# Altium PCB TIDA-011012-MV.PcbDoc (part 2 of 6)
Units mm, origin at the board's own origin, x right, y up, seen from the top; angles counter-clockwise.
Board outline 360 x 280 mm, 4 copper layers (Top Layer, Layer 1, Layer 2, Bottom Layer), stack 2.066 mm thick; 566 components, 345 nets, 1738 pads, 2486 vias.
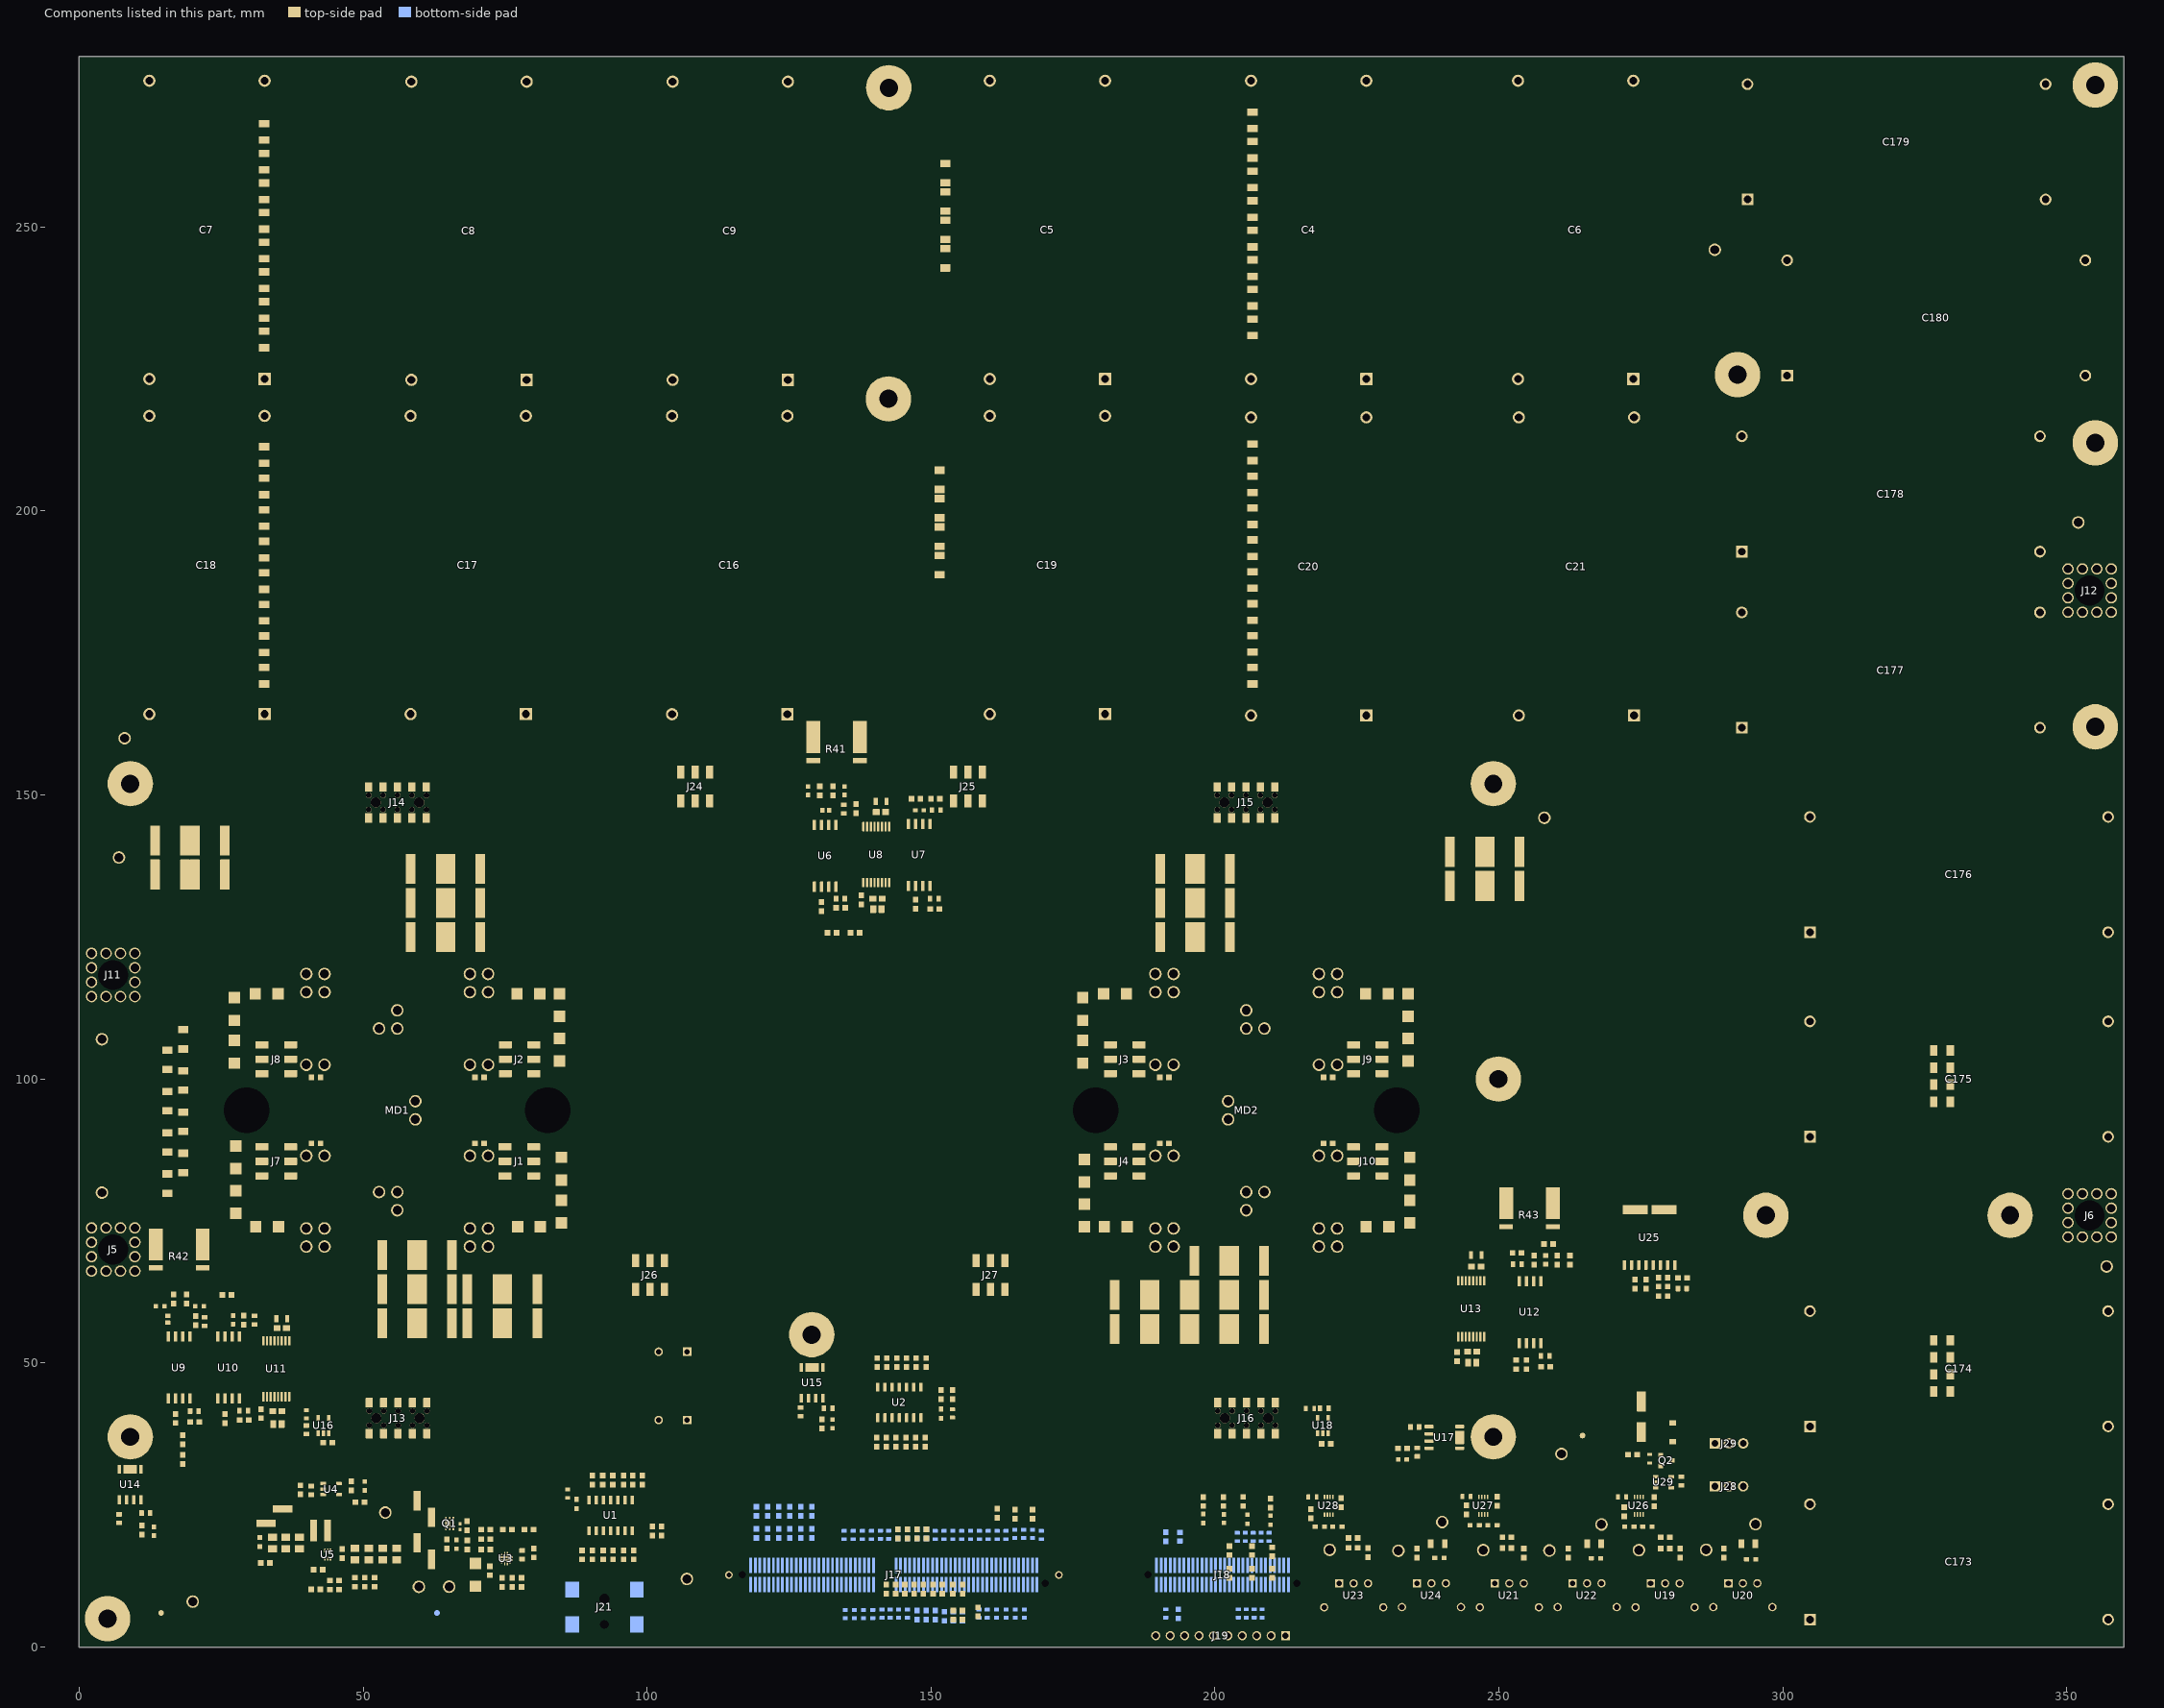
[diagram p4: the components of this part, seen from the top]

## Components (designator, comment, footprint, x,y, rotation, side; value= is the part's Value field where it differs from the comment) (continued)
R133 "ERJ-H3G0R00V" FP-ERJ-H3G0R00V_0603-MFG 209.522,19.382 r90 bottom value=0
R134 "RC0603FR-07470KL" 0603 79.214,20.703 r0 top value=470k
R135 "RC0603FR-0747KL" 0603 71.593,17.176 r180 top value=47.0k
R136 "RC0603FR-071K1L" 0603 76.246,11.376 r90 top value=1.10k
R137 "RC0603FR-075K6L" 0603 71.586,18.961 r0 top value=5.60k
R138 "RC0603FR-0711KL" 0603 75.385,20.693 r0 top value=11.0k
R139 "RC0603FR-0747KL" 0603 68.335,18.007 r270 top value=47.0k
R140 "RC0603FR-072KL" 0603 64.771,18.161 r270 top value=2.00k
R141 "RC0603FR-0747KL" 0603 71.588,20.693 r0 top value=47.0k
R142 "RC0603FR-0715KL" 0603 68.321,21.374 r270 top value=15.0k
R143 "RC0603FR-0747KL" 0603 52.016,11.423 r270 top value=47.0k
R144 "RC0603FR-07220KL" 0603 44.943,10.123 r0 top value=220k
R145 "RG1608P-103-B-T5" 0603 50.275,11.423 r270 top value=10.0k
R146 "RC0603FR-0730KL" 0603 41.644,10.148 r0 top value=30.0k
R147 "CRCW0603499RFKEAC" 0603 32.802,14.815 r180 top value=499
R148 "CRCW0603499RFKEAC" 0603 49.411,25.501 r0 top value=499
R149 "ERJ-3EKF1002V" 0603 153.922,5.621 r270 top value=10.0k
R150 "ERJ-3EKF1002V" 0603 155.522,5.621 r270 top value=10.0k
R151 "TNPW060310R0BEEA" 0603 132.731,150.763 r270 top value=10.0
R152 "TNPW060310R0BEEA" 0603 130.413,150.763 r270 top value=10.0
R153 "RC0603FR-0740R2L" 0603 130.731,130.391 r270 top value=40.2
R154 "RC0603FR-07100RL" 0603 132.566,125.743 r180 top value=100
R155 "CHV1206-FX-1504ELF" FP-CHV1206-FX-1504ELF_1206-MFG 152.5,259.5 r270 top value=1.5M
R156 "CHV1206-FX-1504ELF" FP-CHV1206-FX-1504ELF_1206-MFG 152.5,254.5 r270 top value=1.5M
R157 "CHV1206-FX-1504ELF" FP-CHV1206-FX-1504ELF_1206-MFG 152.5,249.5 r270 top value=1.5M
R158 "CHV1206-FX-1504ELF" FP-CHV1206-FX-1504ELF_1206-MFG 152.5,244.5 r270 top value=1.5M
R159 "CHV1206-FX-1504ELF" FP-CHV1206-FX-1504ELF_1206-MFG 151.5,205.5 r270 top value=1.5M
R160 "CHV1206-FX-1504ELF" FP-CHV1206-FX-1504ELF_1206-MFG 151.5,200.5 r270 top value=1.5M
R161 "CHV1206-FX-1504ELF" FP-CHV1206-FX-1504ELF_1206-MFG 151.5,195.5 r270 top value=1.5M
R162 "CHV1206-FX-1504ELF" FP-CHV1206-FX-1504ELF_1206-MFG 151.5,190.5 r270 top value=1.5M
R163 "RC0603FR-0740R2L" 0603 147.266,130.807 r270 top value=40.2
R164 "RC0603FR-074K7L" 0603 147.327,149.343 r0 top value=4.70k
R165 "RC0603JR-0718KL" 0603 137.728,131.528 r270 top value=18k
R166 "TNPW060310R0BEEA" 0603 16.6,61.3 r270 top value=10.0
R167 "TNPW060310R0BEEA" 0603 18.938,61.3 r270 top value=10.0
R168 "RC0603FR-0740R2L" 0603 16.965,40.25 r270 top value=40.2
R169 "RC0603FR-07100RL" 0603 18.235,36.521 r90 top value=100
R170 "CHV1206-FX-1504ELF" FP-CHV1206-FX-1504ELF_1206-MFG 18.319,107 r270 top locked value=1.5M
R171 "CHV1206-FX-1504ELF" FP-CHV1206-FX-1504ELF_1206-MFG 15.5,103.371 r270 top locked value=1.5M
R172 "CHV1206-FX-1504ELF" FP-CHV1206-FX-1504ELF_1206-MFG 18.319,99.743 r270 top locked value=1.5M
R173 "CHV1206-FX-1504ELF" FP-CHV1206-FX-1504ELF_1206-MFG 15.5,96.114 r270 top locked value=1.5M
R174 "CHV1206-FX-1504ELF" FP-CHV1206-FX-1504ELF_1206-MFG 18.319,92.486 r270 top locked value=1.5M
R175 "CHV1206-FX-1504ELF" FP-CHV1206-FX-1504ELF_1206-MFG 15.5,88.857 r270 top locked value=1.5M
R176 "CHV1206-FX-1504ELF" FP-CHV1206-FX-1504ELF_1206-MFG 18.319,85.229 r270 top locked value=1.5M
R177 "CHV1206-FX-1504ELF" FP-CHV1206-FX-1504ELF_1206-MFG 15.5,81.6 r270 top locked value=1.5M
R178 "RC0603FR-0740R2L" 0603 25.665,40.221 r270 top value=40.2
R179 "RC0603FR-074K7L" 0603 26,62 r180 top value=4.70k
R180 "RC0603JR-0718KL" 0603 32,41.096 r270 top value=18k
R181 "TNPW060310R0BEEA" 0603 262.5,68.122 r270 top value=10.0
R182 "TNPW060310R0BEEA" 0603 258.699,70.95 r180 top value=10.0
R183 "RC0603FR-0740R2L" 0603 254.83,49.728 r270 top value=40.2
R184 "ERJ-3EKF1001V" 0603 253.182,69.397 r0 top value=1.00k
R185 "RC0603JR-0718KL" 0603 242.615,51.153 r270 top value=18k
R186 "ERJ-3GEYJ470V" 0603 11.016,20.59 r90 top value=47
R187 "RT0603BRD07200RL" 0603 273.525,33.855 r0 top value=200
R188 "CRCW060310K0JNEBC" FP-CRCW060310K0JNEBC_0603-MFG 276.53,33.13 r90 top value=10k
R189 "ERJ-3GEYJ470V" 0603 130.81,39.31 r90 top value=47
R190 "RC0603FR-07680RL" 0603 43.754,36 r0 top value=680
R191 "ERJ-3GEYJ470V" 0603 233,35 r0 top value=47
R192 "RC0603FR-07680RL" 0603 219.559,35.777 r0 top value=680
R193 "RC0603FR-07390RL" 0603 279.3,19.35 r0 top value=390
R194 "RC0603FR-07120RL" 0603 281.917,16.525 r270 top value=120
R195 "CRCW060347R0JNEA" 0603 289.606,16.525 r90 top value=47
R196 "RC0603FR-07390RL" 0603 251.404,19.325 r0 top value=390
R197 "RC0603FR-07120RL" 0603 254.369,16.55 r270 top value=120
R198 "CRCW060347R0JNEA" 0603 262.187,16.55 r90 top value=47
R199 "CRCW060368R1FKEA" 0603 275.865,63.925 r270 top value=68.1
R200 "CRCW12064R70JNEA" 1206 328,54 r0 top value=4.7
R201 "CRCW12064R70JNEA" 1206 328,51 r0 top value=4.7
R202 "RC0603JR-078K2L" 0603 278.895,61.775 r180 top value=8.2k
R203 "RC0603JR-071K2L" 0603 278.895,63.45 r0 top value=1.2k
R204 "ERJ-3EKF1002V" 0603 102.546,20.432 r90 top value=10.0k
R205 "ERJ-3EKF1002V" 0603 153.763,44.458 r90 top value=10.0k
R206 "CRCW12064R70JNEA" 1206 328,48 r0 top value=4.7
R207 "CRCW12064R70JNEA" 1206 328,45 r0 top value=4.7
R208 "RC0603FR-07390RL" 0603 224.328,17.463 r0 top value=390
R209 "RC0603FR-07120RL" 0603 226.951,16.609 r270 top value=120
R210 "CRCW060347R0JNEA" 0603 235.561,16.553 r90 top value=47
R211 "CRCW12064R70JNEA" 1206 328,105 r0 top value=4.7
R212 "CRCW12064R70JNEA" 1206 328,102 r0 top value=4.7
R213 "CRCW12064R70JNEA" 1206 328,99 r0 top value=4.7
R214 "CRCW12064R70JNEA" 1206 328,96 r0 top value=4.7
R215 "ERJ-H3G0R00V" FP-ERJ-H3G0R00V_0603-MFG 271.681,26.445 r0 top value=0
R216 "ERJ-H3G0R00V" FP-ERJ-H3G0R00V_0603-MFG 244.28,26.495 r0 top value=0
R217 "ERJ-H3G0R00V" FP-ERJ-H3G0R00V_0603-MFG 217.152,26.419 r0 top value=0
R218 "ERJ-H3G0R00V" FP-ERJ-H3G0R00V_0603-MFG 40,41 r270 top value=0
R219 "ERJ-H3G0R00V" FP-ERJ-H3G0R00V_0603-MFG 216.725,42 r0 top value=0
TP1 "5010" Keystone5010 65.146,10.623 r0 top
TP2 "5011" Keystone5011 59.808,10.596 r0 top
TP3 "5010" Keystone5010 53.895,23.678 r0 top
TP4 "5122" Keystone5122 274.649,17.075 r0 top
TP5 "5122" Keystone5122 295.158,21.641 r0 top
TP6 "5122" Keystone5122 286.492,17.112 r0 top
TP7 "5122" Keystone5122 247.231,17.075 r0 top
TP8 "5122" Keystone5122 268.06,21.578 r0 top
TP9 "5122" Keystone5122 258.87,17 r0 top
TP10 "5122" Keystone5122 220.19,17.112 r0 top
TP11 "5122" Keystone5122 240,22 r0 top
TP12 "5122" Keystone5122 232.3,16.95 r0 top
TP13 "5010" Keystone5010 7,139 r0 top
TP14 "5010" Keystone5010 258,146 r0 top
TP15 "5122" Keystone5122 4,80 r0 top
TP16 "5122" Keystone5122 357,67 r0 top
TP17 "5011" Keystone5011 8,160 r0 top
TP18 "5011" Keystone5011 288,246 r0 top
TP19 "5122" Keystone5122 4,107 r0 top
TP20 "5122" Keystone5122 352,198 r0 top
TP21 "5011" Keystone5011 107,12 r0 top
TP22 "5011" Keystone5011 20,8 r0 top
TP23 "5011" Keystone5011 261,34 r0 top
U1 "SN74HCS126DR" D0014A-MFG 93.546,23.184 r90 top
U2 "SN74HCS126DR" D0014A-MFG 144.432,43.075 r270 top
U3 "TPS259474LRPWT" RPW0010A-MFG 75.16,15.574 r270 top
U4 "TLV75533PDBVR" DBV0005A_N 44.357,27.815 r0 top
U5 "TPS563203DRLR" DRL0006A-MFG 43.759,16.301 r270 top
U6 "AMC0306M05-Q1" DWV0008A-MFG 131.366,139.313 r270 top locked
U7 "AMC1336DWVR" DWV0008A 147.901,139.463 r270 top locked
U8 "UCC33421DHAR" DHA0016A-MFG 140.366,139.513 r90 top locked
U9 "AMC0306M05-Q1" DWV0008A-MFG 17.6,49.2 r270 top locked
U10 "AMC1336DWVR" DWV0008A 26.3,49.2 r270 top
U11 "UCC33421DHAR" DHA0016A-MFG 34.7,49 r90 top locked
U12 "AMC23C12DWVR" DWV0008A-MFG 255.465,58.95 r270 top locked
U13 "UCC33421DHAR" DHA0016A-MFG 245.115,59.557 r90 top locked
U14 "ISOTMP35BEDFQRQ1" DFQ0007A-MFG 8.985,28.616 r90 top locked
U15 "ISOTMP35BEDFQRQ1" DFQ0007A-MFG 129.056,46.531 r90 top
U16 "TLV9001IDBVR" DBV0005A_N 43,39 r90 top
U17 "ISOTMP35BEDFQRQ1" DFQ0007A-MFG 240.383,36.913 r0 top
U18 "TLV9001IDBVR" DBV0005A_N 219,39 r90 top
U19 "TOTX1350(F)" FP-TOTX1350(F)_REC_OPT_PTH-MFG 279.248,7.151 r0 bottom
U20 "TORX1350A(F)" FP-TORX1350A(F)_OPTIC_RECIEVER_13MM0_13MM5-MFG 292.939,7.176 r0 bottom
U21 "TOTX1350(F)" FP-TOTX1350(F)_REC_OPT_PTH-MFG 251.829,7.151 r0 bottom
U22 "TORX1350A(F)" FP-TORX1350A(F)_OPTIC_RECIEVER_13MM0_13MM5-MFG 265.52,7.176 r0 bottom
U23 "TOTX1350(F)" FP-TOTX1350(F)_REC_OPT_PTH-MFG 224.411,7.151 r0 bottom
U24 "TORX1350A(F)" FP-TORX1350A(F)_OPTIC_RECIEVER_13MM0_13MM5-MFG 238.101,7.176 r0 bottom
U25 "TMCS1133B1QDVGR" DVG0010A-MFG 276.5,72.122 r270 top
U26 "TXU0202DCU" DCU0008A-MFG 274.631,24.895 r270 top
U27 "TXU0202DCU" DCU0008A-MFG 247.231,24.895 r270 top
U28 "TXU0202DCU" DCU0008A-MFG 220.019,24.869 r270 top
U29 "SN74LV1T34DBVR" DBV0005A_N 278.967,29.019 r0 top
ZZ1 "This Assembly Note is for PCB labels only" AssemblyNoteLabel 326.87,114.396 r90 top
ZZ2 "These assemblies are ESD sensitive, ESD precautions shall be observed." AssemblyNote 323.07,177.096 r90 top
ZZ3 "These assemblies must be clean and free from flux and all contaminants. Use of no clean flux is not acceptable." AssemblyNote 319.27,137.696 r90 top
ZZ4 "These assemblies must comply with workmanship standards IPC-A-610 Class 2, unless otherwise specified." AssemblyNote 315.47,145.996 r90 top

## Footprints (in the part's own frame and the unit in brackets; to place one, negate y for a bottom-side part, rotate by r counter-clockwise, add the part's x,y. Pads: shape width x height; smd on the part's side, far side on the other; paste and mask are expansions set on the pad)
0402L [mm] "0402 from SM-752 data"
  rect 0.6x0.5 smd: 1(-0.5,0) 2(0.5,0)
  body extent -0.55,-0.3 0.55,0.3, height 0.6
0603 [mm] "0603 from SM-752 data"
  rect 1x0.95 smd: 1(-0.8,0) 2(0.8,0)
  silkscreen extent -1.52,-0.69 1.52,0.69, body extent -0.87,-0.47 0.87,0.47, height 1
0805_HV [mil] "0805 with 30mil clearance between pads"
  rect 50x63 smd: 1(-40,0) 2(40,0)
  silkscreen extent -74,-40 74,40, body extent -43,-29 43,29, height 57
1206 [mm] "1206 from SM-752 data"
  rect 1.3x1.85 smd: 1(-1.45,0) 2(1.45,0)
  silkscreen extent -2.4,-1.21 2.4,1.21, body extent -1.7,-0.9 1.7,0.9, height 1.35
AssemblyNote [mm] "Assembly Note"
AssemblyNoteLabel [mm] "Assembly Note for PCB Labels"
CAPPR5-10x16 [mm] "Capacitor, Electrolytic, Radial; Body 10 x 16 mm (Dia.xH typ); Pin Spacing 5 mm (typ)"
  rect 1.5x1.5 hole 0.9: 1(-2.5,0)
  round 1.5 hole 0.9: 2(2.5,0)
  silkscreen extent -5,-5 5,5, body extent -5.02,-5.03 5.03,5.02, height 16.29
CE_Mark_5mm [mm] "Minimum text height for CE Mark"
  silkscreen extent -3.5,-2.5 3.5,2.5
controlCARD-120HSEC [mm] "Pads are not numbered according to Samtec datasheet."
  rect 0.5x2.724 smd: 1(-23.357,-1.678) 2(-23.357,1.722) 3(-22.557,-1.678) 4(-22.557,1.722) 5(-21.757,-1.678) 6(-21.757,1.722) 7(-20.957,-1.678) 8(-20.957,1.722) 9(-20.157,-1.678) 10(-20.157,1.722) 11(-19.357,-1.678) 12(-19.357,1.722) 13(-18.557,-1.678) 14(-18.557,1.722) 15(-17.757,-1.678) 16(-17.757,1.722) 17(-16.957,-1.678) 18(-16.957,1.722) 19(-16.157,-1.678) 20(-16.157,1.722) 21(-15.357,-1.678) 22(-15.357,1.722) 23(-14.557,-1.678) 24(-14.557,1.722) 25(-13.757,-1.678) 26(-13.757,1.722) 27(-12.957,-1.678) 28(-12.957,1.722) 29(-12.157,-1.678) 30(-12.157,1.722) 31(-11.357,-1.678) 32(-11.357,1.722) 33(-10.557,-1.678) 34(-10.557,1.722) 35(-9.757,-1.678) 36(-9.757,1.722) 37(-8.957,-1.678) 38(-8.957,1.722) 39(-8.157,-1.678) 40(-8.157,1.722) 41(-7.357,-1.678) 42(-7.357,1.722) 43(-6.557,-1.678) 44(-6.557,1.722) 45(-5.757,-1.678) 46(-5.757,1.722) 47(-4.957,-1.678) 48(-4.957,1.722) 49(-4.157,-1.678) 50(-4.157,1.722) 51(-3.357,-1.678) 52(-3.357,1.722) 53(-2.557,-1.678) 54(-2.557,1.722) 55(-1.757,-1.678) 56(-1.757,1.722) 57(2.243,-1.678) 58(2.243,1.722) 59(3.043,-1.678) 60(3.043,1.722) 61(3.843,-1.678) 62(3.843,1.722) 63(4.643,-1.678) 64(4.643,1.722) 65(5.443,-1.678) 66(5.443,1.722) 67(6.243,-1.678) 68(6.243,1.722) 69(7.043,-1.678) 70(7.043,1.722) 71(7.843,-1.678) 72(7.843,1.722) 73(8.643,-1.678) 74(8.643,1.722) 75(9.443,-1.678) 76(9.443,1.722) 77(10.243,-1.678) 78(10.243,1.722) 79(11.043,-1.678) 80(11.043,1.722) 81(11.843,-1.678) 82(11.843,1.722) 83(12.643,-1.678) 84(12.643,1.722) 85(13.443,-1.678) 86(13.443,1.722) 87(14.243,-1.678) 88(14.243,1.722) 89(15.043,-1.678) 90(15.043,1.722) 91(15.843,-1.678) 92(15.843,1.722) 93(16.643,-1.678) 94(16.643,1.722) 95(17.443,-1.678) 96(17.443,1.722) 97(18.243,-1.678) 98(18.243,1.722) 99(19.043,-1.678) 100(19.043,1.722) 101(19.843,-1.678) 102(19.843,1.722) 103(20.643,-1.678) 104(20.643,1.722) 105(21.443,-1.678) 106(21.443,1.722) 107(22.243,-1.678) 108(22.243,1.722) 109(23.043,-1.678) 110(23.043,1.722) 111(23.843,-1.678) 112(23.843,1.722) 113(24.643,-1.678) 114(24.643,1.722) 115(25.443,-1.678) 116(25.443,1.722) 117(26.243,-1.678) 118(26.243,1.722) 119(27.043,-1.678) 120(27.043,1.722)
  round 0.025 hole 1.27 unplated mask+0.876: 181(-24.857,0.022) 182(28.543,1.522)
  round 1.348 hole 0.84: 185(-27.207,0.022) 186(30.893,0.022)
  silkscreen extent -32.11,-3.86 35.8,3.9, body extent -31.75,-3.47 35.3,3.53, height 12.35
controlCARD-180HSEC-60pinAddon [mm] "Pads are not numbered according to datasheet."
  round 0.025 hole 1.27 unplated mask+0.876: 61(-13.1,0) 62(13.1,1.5)
  rect 0.5x2.724 smd: 121(-11.6,-1.7) 122(-11.6,1.7) 123(-10.8,-1.7) 124(-10.8,1.7) 125(-10,-1.7) 126(-10,1.7) 127(-9.2,-1.7) 128(-9.2,1.7) 129(-8.4,-1.7) 130(-8.4,1.7) 131(-7.6,-1.7) 132(-7.6,1.7) 133(-6.8,-1.7) 134(-6.8,1.7) 135(-6,-1.7) 136(-6,1.7) 137(-5.2,-1.7) 138(-5.2,1.7) 139(-4.4,-1.7) 140(-4.4,1.7) 141(-3.6,-1.7) 142(-3.6,1.7) 143(-2.8,-1.7) 144(-2.8,1.7) 145(-2,-1.7) 146(-2,1.7) 147(-1.2,-1.7) 148(-1.2,1.7) 149(-0.4,-1.7) 150(-0.4,1.7) 151(0.4,-1.7) 152(0.4,1.7) 153(1.2,-1.7) 154(1.2,1.7) 155(2,-1.7) 156(2,1.7) 157(2.8,-1.7) 158(2.8,1.7) 159(3.6,-1.7) 160(3.6,1.7) 161(4.4,-1.7) 162(4.4,1.7) 163(5.2,-1.7) 164(5.2,1.7) 165(6,-1.7) 166(6,1.7) 167(6.8,-1.7) 168(6.8,1.7) 169(7.6,-1.7) 170(7.6,1.7) 171(8.4,-1.7) 172(8.4,1.7) 173(9.2,-1.7) 174(9.2,1.7) 175(10,-1.7) 176(10,1.7) 177(10.8,-1.7) 178(10.8,1.7) 179(11.6,-1.7) 180(11.6,1.7)
  silkscreen extent -14.68,-3.88 14.68,3.88, body extent -14.3,-3.5 14.3,3.5, height 7.95
CUI_PJ-002AH-SMT [mm] "CUI"
  rect 2.8x2.4 smd: 1(-3.05,5.7) 1A(3.05,5.7) 2(-3.05,-5.7) 3(3.05,-5.7)
  round 1 hole 1.6 unplated: MH1(-3.05,0)
  round 1.524 hole 1.8 unplated: MH2(1.45,0)
  silkscreen extent -8.05,-4.5 6.75,5.45, body extent -8.05,-6.3 6.75,6.3, height 11.2
D0014A-MFG [mm]
  rrect17% 1.55x0.6 smd paste-1000 mask+0: 1(-2.7,3.81) 2(-2.7,2.54) 3(-2.7,1.27) 4(-2.7,0) 5(-2.7,-1.27) 6(-2.7,-2.54) 7(-2.7,-3.81) 8(2.7,-3.81) 9(2.7,-2.54) 10(2.7,-1.27) 11(2.7,0) 12(2.7,1.27) 13(2.7,2.54) 14(2.7,3.81)
  silkscreen extent -4.15,-4.38 1.55,4.38, body extent -3.57,-4.62 3.57,4.62, height 0.25
DBV0005A_N [mm] "SOT23, 5-Leads, Body 2.9x1.6mm, Pitch 0.95mm, Lead Span 2.8mm, IPC Medium Density"
  rrect17% 1x0.6 smd: 1(-1.375,0.95) 2(-1.375,0) 3(-1.375,-0.95) 4(1.375,-0.95) 5(1.375,0.95)
  silkscreen extent -0.25,-1.55 0.25,1.55, body extent -1.42,-1.46 1.42,1.46, height 1.09
DCU0008A-MFG [mm]
  rrect33% 0.8x0.3 smd paste-1000 mask+0: 1(-1.55,0.75) 2(-1.55,0.25) 3(-1.55,-0.25) 4(-1.55,-0.75) 5(1.55,-0.75) 6(1.55,-0.25) 7(1.55,0.25) 8(1.55,0.75)
  silkscreen extent -2.62,-1.05 0.78,1.05, body extent -2.05,-1.3 2.05,1.3, height 0.25
DFQ0007A-MFG [mm]
  rrect17% 1.55x0.6 smd paste+0 mask+0: 1(-2.7,1.905) 2(-2.7,0.635) 3(-2.7,-0.635) 4(-2.7,-1.905) 5(2.7,-1.905) 7(2.7,1.905)
  rrect6% 1.55x2.36 smd paste+0 mask+0: 6(2.7,0)
  silkscreen extent -4.14,-2.5 1.55,2.5, body extent -3.57,-2.75 3.57,2.75, height 0.25
DHA0016A-MFG [mm]
  rrect24% 1.65x0.41 smd paste+0 mask+0: 1(-4.925,2.275) 2(-4.925,1.625) 3(-4.925,0.975) 4(-4.925,0.325) 5(-4.925,-0.325) 6(-4.925,-0.975) 7(-4.925,-1.625) 8(-4.925,-2.275) 9(4.925,-2.275) 10(4.925,-1.625) 11(4.925,-0.975) 12(4.925,-0.325) 13(4.925,0.325) 14(4.925,0.975) 15(4.925,1.625) 16(4.925,2.275)
  silkscreen extent -6.42,-2.98 3.5,2.98, body extent -5.85,-3.22 5.85,3.22, height 0.25
DQK0006C [mm] "WSON"
  rrect12% 0.9x0.86 on Top Paste: 0(0,0.325)
  rrect34% 0.7x0.29 on Top Paste: 0(0.095,-0.65)
  rrect33% 0.45x0.3 smd: 1(-0.975,0.65) 2(-0.975,0) 3(-0.975,-0.65) 4(0.975,-0.65) 5(0.975,0) 6(0.975,0.65)
  rrect33% 0.75x0.3 smd paste-0.15: 7(0.095,-0.65)
  rrect11% 1x0.95 smd paste-0.5: 8(0,0.325)
  silkscreen extent -1.15,-1.15 1.15,1.15, body extent -1,-1 1,1, height 0.82
DRL0006A-MFG [mm]
  rrect33% 0.67x0.3 smd paste+0 mask+0: 1(-0.74,0.5) 2(-0.74,0) 3(-0.74,-0.5) 4(0.74,-0.5) 5(0.74,0) 6(0.74,0.5)
  silkscreen extent -1.75,-1.05 0.65,1.05, body extent -1.17,-1.1 1.17,1.1, height 0.25
DVG0010A-MFG [mm]
  rrect6% 1.65x4.41 smd paste+0 mask+0: 1(-4.875,2.54) 2(-4.875,-2.54)
  rrect17% 1.65x0.6 smd paste+0 mask+0: 3(4.875,-4.445) 4(4.875,-3.175) 5(4.875,-1.905) 6(4.875,-0.635) 7(4.875,0.635) 8(4.875,1.905) 9(4.875,3.175) 10(4.875,4.445)
  silkscreen extent -6.37,-5.25 3.67,5.25, body extent -5.8,-5.5 5.8,5.5, height 0.25
DWV0008A [mm] "SOIC, 8-Leads, Body 5.95x7.6mm (max), Pitch 1.27mm"
  rrect17% 1.8x0.6 smd: 1(-5.45,1.905) 2(-5.45,0.635) 3(-5.45,-0.635) 4(-5.45,-1.905) 5(5.45,-1.905) 6(5.45,-0.635) 7(5.45,0.635) 8(5.45,1.905)
  silkscreen extent -6.25,-2.95 2.98,2.95, body extent -5.77,-2.92 5.77,2.93, height 2.67
DWV0008A-MFG [mm] "Recommended Land Pattern"
  rrect17% 1.8x0.6 smd paste+0 mask+0: 1(-5.45,1.905) 2(-5.45,0.635) 3(-5.45,-0.635) 4(-5.45,-1.905) 5(5.45,-1.905) 6(5.45,-0.635) 7(5.45,0.635) 8(5.45,1.905)
  silkscreen extent -7.1,-2.98 3.8,2.98, body extent -5.75,-2.93 5.75,2.93, height 2.8
FCC_disclaimer [mm]
Fiducial10-20 [mm]
  round 1 smd mask+0.5: 1(0,0)
  Top Layer keep-out circle w1.178: c0,0 r0.5
FP-0603ZC102KAT2A_0603-MFG [mm]
  rrect13% 0.8x0.75 smd paste+0 mask+0: 1(-0.75,0) 2(0.75,0)
  silkscreen extent -0.87,-0.77 0.87,0.77, body extent -1.25,-0.58 1.25,0.58, height 0.25
FP-06031C101JAT2A_0603-MFG [mm]
  rrect13% 0.8x0.75 smd paste+0 mask+0: 1(-0.75,0) 2(0.75,0)
  silkscreen extent -0.87,-0.77 0.87,0.77, body extent -1.25,-0.58 1.25,0.58, height 0.25
FP-0022111031_HDR3-MFG [mm]
  rrect5% 1.85x1.85 hole 1.2 paste-2539.97 mask+0: 1(2.5,0.3)
  round 1.85 hole 1.2 paste-2539.97 mask+0: 2(0,0.3) 3(-2.5,0.3)
  silkscreen extent -4.1,-3.1 4.7,3.1, body extent -3.5,-2.9 3.5,2.9, height 12.1
FP-74439324047_SMD2-MFG [mm] "Recommended Land Pattern"
  rrect8% 1.2x3.8 smd paste+0 mask+0: 1(-1.225,0) 2(1.225,0)
  silkscreen extent -2.88,-2.25 0.25,2.25, body extent -2.15,-2.15 2.15,2.15, height 3.2
FP-C4AQPEW5450M3BJ_RADIAL-MFG [mm] "Recommended Land Pattern"
  round 2.15 hole 1.4 paste-2539.97 mask+0: 1(-26.25,-10.15) 2(26.25,-10.15) 2(26.25,10.15)
  rrect5% 2.15x2.15 hole 1.4 paste-2539.97 mask+0: 1(-26.25,10.15)
  silkscreen extent -29.15,-22.75 29.15,22.75, body extent -28.75,-22.5 28.75,22.5, height 65.3
FP-C4ASPBW4250A3MJ_RADIAL-MFG [mm] "Recommended Land Pattern"
  round 2.05 hole 1.35 paste-2539.97 mask+0: 1(-26.25,-10.15) 2(26.25,-10.15) 2(26.25,10.15)
  rrect5% 2.05x2.05 hole 1.35 paste-2539.97 mask+0: 1(-26.25,10.15)
  silkscreen extent -28.75,-15 28.75,15, body extent -28.75,-15 28.75,15, height 45
FP-C0603C103J3GAC7867_0603-MFG [mm]
  rrect13% 0.75x0.9 smd paste+0 mask+0: 1(-0.6,0) 2(0.6,0)
  silkscreen extent -0.87,-0.82 0.87,0.82, body extent -1.2,-0.6 1.2,0.6, height 0.25
FP-C0603C153K5RACTU_0603-IPC_A [mil]
  rrect9% 47.5x41.66 smd paste+0 mask+0: 1(-32.51,0) 2(32.51,0)
  body extent -76,-41 76,41, height 10
FP-C2220X103KHRAC7800_2220-MFG [mm] "Recommended Land Pattern"
  rrect6% 1.7x5.3 smd paste+0 mask+0: 1(-2.65,0) 2(2.65,0)
  silkscreen extent -1.43,-2.7 1.43,2.7, body extent -2.95,-2.5 2.95,2.5, height 2.2
FP-CHV1206-FX-1504ELF_1206-MFG [mm]
  rrect8% 1.3x1.8 smd paste+0 mask+0: 1(-1.7,0) 2(1.7,0)
  silkscreen extent -0.67,-0.85 0.67,0.85, body extent -2.45,-1 2.45,1, height 0.25
FP-CL10B104KA8VPJC_0603-MFG [mm]
  rrect13% 0.79x1 smd paste+0 mask+0: 1(-0.755,0) 2(0.755,0)
  silkscreen extent -0.9,-0.87 0.9,0.87, body extent -1.25,-0.6 1.25,0.6, height 0.25
FP-CL10B105KA8VPJC_0603-MFG [mm]
  rrect13% 0.79x1 smd paste+0 mask+0: 1(-0.755,0) 2(0.755,0)
  silkscreen extent -0.9,-0.87 0.9,0.87, body extent -1.25,-0.6 1.25,0.6, height 0.25
FP-CRCW060310K0JNEBC_0603-MFG [mm]
  rrect20% 0.5x0.9 smd paste+0 mask+0: 1(-0.75,0) 2(0.75,0)
  silkscreen extent -0.13,-0.45 0.13,0.45, body extent -1.1,-0.55 1.1,0.55, height 0.25
FP-DMN3042L-13_SOT23-MFG [mm]
  rrect13% 0.9x0.8 smd paste+0 mask+0: 1(-1,0.95) 2(-1,-0.95) 3(1,0)
  silkscreen extent -0.7,-1.5 0.7,1.5, body extent -1.55,-1.6 1.55,1.6, height 0.25
FP-ERJ-H3G0R00V_0603-IPC_B [mm]
  rrect10% 0.957x0.962 smd paste+0 mask+0: 1(-0.751,0) 2(0.751,0)
  silkscreen extent -1.23,-0.88 1.23,0.88, body extent -0.8,-0.4 0.8,0.4, height 0.55
FP-ERJ-H3G0R00V_0603-MFG [mm]
  rrect15% 0.65x0.9 smd paste+0 mask+0: 1(-0.725,0) 2(0.725,0)
  silkscreen extent 0,-0.48 0,0.48, body extent -0.8,-0.4 0.8,0.4, height 0.55
FP-G4H22MT33GB4_SiCPAK-G+_MODIFIED-MFG [mm] "Recommended Land Pattern Modified"
  round 2.2 hole 1.6 paste-2539.97 mask+0: AC1(20.8,12.8) AC1(20.8,16) AC1(24,12.8) AC1(24,16) AC2(-24,12.8) AC2(-24,16) AC2(-20.8,12.8) AC2(-20.8,16) DC1+(20.8,-16) DC1+(20.8,-12.8) DC1+(24,-16) DC1+(24,-12.8) DC1-(14.4,0) DC1-(14.4,3.2) DC1-(17.6,0) DC2+(-24,-16) DC2+(-24,-12.8) DC2+(-20.8,-16) DC2+(-20.8,-12.8) DC2-(-17.6,0) DC2-(-14.4,0) DC2-(-14.4,3.2) G1(8,-12.8) G2(8,12.8) G3(-8,-12.8) G4(-8,12.8) KS1(8,-16) KS2(8,16) KS3(-8,-16) KS4(-8,16) T1(-1.6,-3.2) T2(1.6,-3.2)
  round 4.6 hole 8 unplated paste-2539.97 mask+0: ""(0,-26.5) ""(0,26.5)
  silkscreen extent -28.45,-24.1 29.12,24.1, body extent -28.35,-32.49 28.35,32.51, height 12.9
FP-GMC10X7R104K25NT_0603-MFG [mil]
  rrect13% 35x30 smd paste+0 mask+0: 1(-32.5,0) 2(32.5,0)
  silkscreen extent -35,-31 35,31, body extent -54,-24 54,24, height 10
FP-GRT21BD71A226ME13L_0805-MFG [mm]
  rrect14% 0.7x1.3 smd paste+0 mask+0: 1(-0.95,0) 2(0.95,0)
  silkscreen extent -0.23,-0.72 0.23,0.72, body extent -1.4,-0.82 1.4,0.82, height 0.25
FP-HLE-105-02-G-DV-BE-A_CONN_RCPT_10-MFG [mm] "Recommended Land Pattern"
  rrect8% 1.27x1.68 smd paste+0 mask+0: 1(5.08,-2.72) 2(5.08,2.72) 3(2.54,-2.72) 4(2.54,2.72) 5(0,-2.72) 6(0,2.72) 7(-2.54,-2.72) 8(-2.54,2.72) 9(-5.08,-2.72) 10(-5.08,2.72)
  round 0.97 hole 0.97 unplated paste-2539.97 mask+0: ""(-5.08,-1.27) ""(-5.08,1.27) ""(-2.54,-1.27) ""(-2.54,1.27) ""(0,1.27) ""(0,-1.27) ""(2.54,-1.27) ""(2.54,1.27) ""(5.08,-1.27) ""(5.08,1.27)
  round 1.78 hole 1.78 unplated paste-2539.97 mask+0: ""(-3.81,0) ""(3.81,0)
  silkscreen extent -6.45,-3.43 6.45,2.61, body extent -6.35,-3.29 6.35,3.29, height 3.79
FP-LSL29K-G1H2-1-Z_0603-0 [mm]
  rrect13% 0.8x0.8 smd paste-1000 mask+0: 1(-0.75,0) 2(0.75,0)
  silkscreen extent -1.77,-0.77 0.7,0.77, body extent -1.25,-0.55 1.25,0.55, height 0.25
FP-MA0805XR106K160_0805-IPC_C [mm]
  rrect9% 1.055x1.356 smd paste+0 mask+0: 1(-0.726,0) 2(0.726,0)
  silkscreen extent -1.25,-1.12 1.25,1.12, body extent -1.35,-0.82 1.35,0.82, height 0.25
FP-TORX1350A(F)_OPTIC_RECIEVER_13MM0_13MM5-MFG [mm]
  rrect7% 1.45x1.45 hole 0.95 paste-2539.97 mask+0: 1(-2.54,-4.05)
  round 1.45 hole 0.95 paste-2539.97 mask+0: 2(0,-4.05) 3(2.54,-4.05) 4(5.2,0.15) 5(-5.2,0.15)
  silkscreen extent -6.65,-7.5 6.65,6.9, body extent -6.5,-6.75 6.5,6.75, height 8.8
FP-TOTX1350(F)_REC_OPT_PTH-MFG [mm]
  rrect7% 1.45x1.45 hole 0.95 paste-2539.97 mask+0: 1(-2.54,-4.05)
  round 1.45 hole 0.95 paste-2539.97 mask+0: 2(0,-4.05) 3(2.54,-4.05) 4(5.2,0.15) 5(-5.2,0.15)
  silkscreen extent -6.65,-7.52 6.65,6.9, body extent -6.5,-6.75 6.5,6.75, height 8.8
IEC_HighVoltage_Medium [mm]
  silkscreen extent -5.51,-4.46 5.51,5.09
IEC_HotSurface_Medium [mm]
  silkscreen extent -5.51,-4.76 5.51,4.78
Keystone5010 [mil] "Keystone Multipurpose loops"
  round 87 hole 63: 1(0,0)
  silkscreen extent -70,-70 70,70, body extent -63,-63 63,62, height 319
Keystone5011 [mil] "Keystone Multipurpose loops"
  round 87 hole 63: 1(0,0)
  silkscreen extent -70,-70 70,70, body extent -63,-63 63,62, height 319
Keystone5122 [mil] "Keystone Compact loops"
  round 87 hole 63: 1(0,0)
  silkscreen extent -70,-70 70,70, body extent -63,-63 62,63, height 225
Label_650x200 [mil] "Thermal Transfer Label"
  round 1 on Mech14: 0(0,0)
  silkscreen extent -325,-100 325,100, body extent -325,-100 325,100, height 1
NLCV25 [mm] "TDK"
  rect 1x1.5 smd: 1(-1.25,0) 2(1.25,0)
  body extent -1.35,-1.05 1.35,1.05, height 1.9
"NY PMS 440 0025 PH" [mm] "4-40 nylon screw and mounting hole"
  round 8 hole 3.2: 1(0,0)
  body extent -3.3,-3.3 3.3,3.3, height 2.69
RPW0010A-MFG [mm]
  round 0.27 smd paste-1000 mask+0: 1(-0.75,0.7) 10(0.75,0.7)
  rrect40% 0.6x0.25 smd paste+0 mask+0: 2(-0.9,0.225) 3(-0.9,-0.225) 8(0.9,-0.225) 9(0.9,0.225)
  round 0.255 smd paste-1000 mask+0: 4(-0.75,-0.75) 7(0.75,-0.75)
  rrect33% 0.3x2.4 smd paste-1000 mask+0: 5(-0.25,0) 6(0.25,0)
  Top Layer region: -0.85,0.85 -0.85,1.15 -0.843,1.175 -0.825,1.193 -0.8,1.2 -0.8,1.2 -0.65,1.2 -0.631,1.196 -0.615,1.185 -0.604,1.169 -0.6,1.15 -0.6,1.15 -0.6,0.6 -0.604,0.581 -0.615,0.565 -0.631,0.554 -0.65,0.55 -0.65,0.55 -1.15,0.55 -1.169,0.554 -1.185,0.565 -1.196,0.581 -1.2,0.6 -1.2,0.6 -1.2,0.8 -1.193,0.825 -1.175,0.843 -1.15,0.85 -1.15,0.85
  Top Layer region: -0.85,-0.85 -0.85,-1.15 -0.846,-1.169 -0.835,-1.185 -0.819,-1.196 -0.8,-1.2 -0.8,-1.2 -0.65,-1.2 -0.631,-1.196 -0.615,-1.185 -0.604,-1.169 -0.6,-1.15 -0.6,-1.15 -0.6,-0.6 -0.604,-0.581 -0.615,-0.565 -0.631,-0.554 -0.65,-0.55 -0.65,-0.55 -1.15,-0.55 -1.169,-0.554 -1.185,-0.565 -1.196,-0.581 -1.2,-0.6 -1.2,-0.6 -1.2,-0.8 -1.196,-0.819 -1.185,-0.835 -1.169,-0.846 -1.15,-0.85 -1.15,-0.85
  Top Layer region: 0.85,-0.85 0.85,-1.15 0.846,-1.169 0.835,-1.185 0.819,-1.196 0.8,-1.2 0.8,-1.2 0.65,-1.2 0.631,-1.196 0.615,-1.185 0.604,-1.169 0.6,-1.15 0.6,-1.15 0.6,-0.6 0.604,-0.581 0.615,-0.565 0.631,-0.554 0.65,-0.55 0.65,-0.55 1.15,-0.55 1.169,-0.554 1.185,-0.565 1.196,-0.581 1.2,-0.6 1.2,-0.6 1.2,-0.8 1.196,-0.819 1.185,-0.835 1.169,-0.846 1.15,-0.85 1.15,-0.85
  Top Layer region: 0.85,0.85 0.85,1.15 0.846,1.169 0.835,1.185 0.819,1.196 0.8,1.2 0.8,1.2 0.65,1.2 0.631,1.196 0.615,1.185 0.604,1.169 0.6,1.15 0.6,1.15 0.6,0.6 0.604,0.581 0.615,0.565 0.631,0.554 0.65,0.55 0.65,0.55 1.15,0.55 1.169,0.554 1.185,0.565 1.196,0.581 1.2,0.6 1.2,0.6 1.2,0.8 1.196,0.819 1.185,0.835 1.169,0.846 1.15,0.85 1.15,0.85
  silkscreen extent -1.87,-1.58 1.05,1.58, body extent -1.3,-1.3 1.3,1.3, height 0.25
Samtec_HLE-103-02-x-DV [mm] "Receptacle, 2.54mm, 3x2, SMT"
  rrect8% 1.27x2.29 smd: 1(-2.54,2.525) 2(-2.54,-2.525) 3(0,2.525) 4(0,-2.525) 5(2.54,2.525) 6(2.54,-2.525)
  body extent -3.81,-3.29 3.81,3.29, height 3.66
Samtec_TSM-102-01-T-SV-P-TR [mil] "SMD, 2-Leads, Body 200x100mil"
  rect 50x135 smd: 1(-50,57.5) 2(50,-57.5)
  silkscreen extent -100,-50 100,92, body extent -100,-96 100,96, height 380
SMA [mm] "Molded Diode, 2-Leads, Body 4.3x2.6mm, IPC Medium Density, based on OnSemi component dimensions and land pattern"
  rect 2x2 smd: 1(-2,0) 2(2,0)
  silkscreen extent -3.66,-1.57 2.79,1.57, body extent -2.6,-1.3 2.6,1.3, height 2.42
SOD-123 [mm] "On Semi recommended land pattern"
  rect 0.915x1.22 smd: 1(-1.637,0) 2(1.637,0)
  silkscreen extent -2.74,-1.17 2.03,1.17, body extent -1.93,-0.9 1.93,0.9, height 1.35
UWT_630x770 [mm] "SMD, 2-Leads, Dia 6.3mm"
  rrect6% 3.5x1.6 smd: 1(-2.7,0) 2(2.7,0)
  body extent -3.5,-3.3 3.5,3.3, height 8
WEEE_Minimum [mm] "WEEElie bin"
  silkscreen extent -2.42,-4.38 2.52,2.65
WL-SMCW_GREEN [mm] "WURTH"
  rect 0.8x0.8 smd: 1(-0.8,0) 2(0.8,0)
  silkscreen extent -1.9,-0.8 1.2,0.8, body extent -0.85,-0.45 0.85,0.45, height 0.8
WSL4026_0p5milli [mm] "VISHAY"
  rect 2.44x5.6 smd: 1(-4.115,-0.89) 2(4.115,-0.89)
  rect 2.44x0.89 smd: 3(-4.115,3.245) 4(4.135,3.245)
  silkscreen extent -5.25,-3.49 5.1,3.51, body extent -5.05,-3.3 5.05,3.3, height 2.96
Wurth_7461086 [mm] "Bush, M4, TH"
  round 2 hole 1.475: 1(-3.81,-3.81) 1(-3.81,-1.27) 1(-3.81,1.27) 1(-3.81,3.81) 1(-1.27,3.81) 1(-1.27,-3.81) 1(1.27,3.81) 1(1.27,-3.81) 1(3.81,-3.81) 1(3.81,-1.27) 1(3.81,1.27) 1(3.81,3.81)
  round 0 hole 5.3 unplated: ""(0,0)
  body extent -4.5,-4.5 4.5,4.5, height 6.1
Wurth_61301011121 [mm] "Header, 2.54mm, 10x1, TH"
  rect 1.6x1.6 hole 1.1: 1(-11.43,0)
  round 1.6 hole 1.1: 2(-8.89,0) 3(-6.35,0) 4(-3.81,0) 5(-1.27,0) 6(1.27,0) 7(3.81,0) 8(6.35,0) 9(8.89,0) 10(11.43,0)
  silkscreen extent -12.7,-1.27 12.7,1.6, body extent -12.7,-1.27 12.7,1.27, height 8.54

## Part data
C1 C2 C3 C11 C12 C13 C14 C15 C23 C24 C25 C26 C65 C71 C161 C163 C164 C165 C166 C167 C168 C181 C182 C183 C184 C185 C186 C187 C188 C189 C190 C191 C192 C193 C194 C195 C196 C197 C198 C199: library part CMP-0128868-1, "10000 pF ±10% 3000V (3kV) Ceramic Capacitor X7R 2220 (5750 Metric)", Digikey Part Number=399-C2220X103KHRACTUCT-ND, Manufacturer=KEMET, Mouser Part Number=80-C2220X103KHR, Operating Temperature Range="-55°C to +125°C", TempCo=15%, Temperature Characteristic=X7R, Tolerance_%=10%, ValueDisplayed=0.01uF
C4 C5 C6 C7 C8 C9 C16 C17 C18 C19 C20 C21: library part CMP-0128781-1, "45 µF Film Capacitor 1200V (1.2kV) Polypropylene (PP), Metallized Radial - 4 Leads", Digikey Part Number=399-C4AQPEW5450M3BJ-ND, Manufacturer=KEMET, Mouser Part Number=80-C4AQPEW5450M3BJ, Operating Temperature Range="-55°C to +105°C", Tolerance_%=5%, ValueDisplayed=45uF
C10 C22 C73 C75 C82 C84 C92 C94 C101 C103 C111 C113 C117 C123 C125 C126 C128 C129 C130 C132 C133 C146: library part CMP-0121051-1, "Automotive CAP, 100㎋, 25V, ±10%, X7R, 0603, 5mm Bending", Manufacturer=Samsung, Mouser Part Number=187-CL10B104KA8VPJC, Operating Temperature Range="-55°C to +125°C", TempCo=15%, Temperature Characteristic=X7R, Tolerance_%=10%, ValueDisplayed=100nF
C27 C28 C29 C30 C32 C33 C34 C35 C36 C37 C38 C39 C40 C41 C42 C43 C44 C46 C47 C48 C49 C50 C51 C52 C53 C54 C81 C100: library part CMP-0006982-4, "CAP, CERM, 220 pF, 50 V, +/- 10%, X7R, 0603", Cap_Case=0603, Manufacturer=Kemet, Supplier Part Number 1=399-5342-1-ND, TempCo=X7R, Tolerance_%=10%, Value1=Unknown, Value2=50V, ValueDisplayed=220pF
C31 C45 C135 C137 C138 C140 C141 C142 C143 C144 C145: library part CMP-0094950-1, "0.1 µF ±10% 25V Ceramic Capacitor X7R 0603 (1608 Metric)", Digikey Part Number=2571-GMC10X7R104K25NTTR-ND, Manufacturer="CAL-CHIP ELECTRONICS", Operating Temperature Range="-55°C to +125°C", TempCo=30ppm/°C, Temperature Characteristic=X7R, Tolerance_%=10%, ValueDisplayed=0.1uF
C55 C56: library part CMP-0010289-1, "CAP, AL, 1000 uF, 16 V, +/- 20%, TH", Cap_Case=10x16, Manufacturer=Rubycon, Supplier Part Number 1=1189-1151-ND, Tolerance_%=20%, Value1=Unknown, Value2=16V, ValueDisplayed=1000uF
C57 C59: library part CMP-0007052-4, "CAP, CERM, 1 uF, 35 V, +/- 10%, X7R, 0603", Cap_Case=0603, Manufacturer=TDK, Supplier Part Number 1=445-7414-1-ND, TempCo=X7R, Tolerance_%=10%, Value1=Unknown, Value2=35V, ValueDisplayed=1uF
C58 C171: library part CMP-0006752-5, "CAP, CERM, 0.1 uF, 25 V, +/- 5%, X7R, 0603", Cap_Case=0603, Manufacturer=AVX, Supplier Part Number 1=478-3713-1-ND, TempCo=X7R, Tolerance_%=5%, Value1="0.05 ohm", Value2=25V, ValueDisplayed=0.1uF
C60: library part CMP-0007477-4, "CAP, CERM, 2700 pF, 100 V, +/- 10%, X7R, 0603", Cap_Case=0603, Manufacturer=MuRata, Supplier Part Number 1=490-1480-1-ND, TempCo=X7R, Tolerance_%=10%, Value1=Unknown, Value2=100V, ValueDisplayed=2700pF
C61: library part CMP-0006985-4, "CAP, CERM, 3300 pF, 50 V, +/- 10%, X7R, 0603", Cap_Case=0603, Manufacturer=Kemet, Supplier Part Number 1=399-5339-1-ND, TempCo=X7R, Tolerance_%=10%, Value1=Unknown, Value2=50V, ValueDisplayed=3300pF
C62: library part CMP-0006659-2, "CAP, CERM, 0.1 uF, 25 V, +/- 10%, X7R, 0402", Cap_Case=0402, Manufacturer=MuRata, Supplier Part Number 1=490-10698-1-ND, TempCo=X7R, Tolerance_%=10%, Value1=Unknown, Value2=25V, ValueDisplayed=0.1uF
C63: library part CMP-0007255-4, "CAP, CERM, 22 pF, 100 V, +/- 5%, C0G/NP0, 0603", Cap_Case=0603, Manufacturer=MuRata, Supplier Part Number 1=490-1335-1-ND, TempCo=C0G/NP0, Tolerance_%=5%, Value1=Unknown, Value2=100V, ValueDisplayed=22pF
C64 C66: library part CMP-0007121-4, "CAP, CERM, 2.2 uF, 16 V, +/- 10%, X7R, 0603", Cap_Case=0603, Manufacturer="Taiyo Yuden", Supplier Part Number 1=EMK107BB7225KA-T-ND, TempCo=X7R, Tolerance_%=10%, Value1=Unknown, Value2=16V, ValueDisplayed=2.2uF
C67 C68 C69: library part CMP-0008377-2, "CAP, CERM, 22 uF, 10 V, +/- 20%, X7R, 0805", Cap_Case=0805, Manufacturer=MuRata, Supplier Part Number 1=81-GRM21BZ71A226ME5L, TempCo=X7R, Tolerance_%=20%, Value1=Unknown, Value2=10V, ValueDisplayed=22uF
C70 C72 C169 C170: library part CMP-0085283-1, "CAP, CERM, 10 µF, 16 V,+/- 10%, X7R, 0805", Cap_Case=0805, Manufacturer="Taiyo Yuden", TempCo=X7R, Tolerance_%=10%, Value2=16V, ValueDisplayed=10µF
C74 C76 C83 C85 C93 C95 C102 C104 C112 C114: library part CMP-0079605-1, "CAP, CERM, 2.2 µF, 16 V,+/- 10%, X7R, 0603", Cap_Case=0603, Manufacturer="Yageo America", Supplier Part Number 1=311-3490-1-ND, TempCo=X7R, Tolerance_%=10%, Value2=16V, ValueDisplayed=2.2µF
C77 C96: library part CMP-0095473-1, "10000 pF ±5% 25V Ceramic Capacitor C0G, NP0 0603 (1608 Metric)", Digikey Part Number=399-C0603C103J3GAC7867CT-ND, Manufacturer=KEMET, Mouser Part Number=80-C0603C103J3G, Operating Temperature Range="-55°C to +125°C", TempCo=30ppm/°C, Temperature Characteristic=C0G, Tolerance_%=5%, ValueDisplayed=10000pF
C78 C87 C97 C106 C116 C147 C148 C149 C150 C151 C152 C153 C154 C155: library part CMP-0006811-4, "CAP, CERM, 10 pF, 10 V, +/- 10%, X7R, 0603", Cap_Case=0603, Manufacturer=AVX, Supplier Part Number 1=0603ZC100KAT2A-ND, TempCo=X7R, Tolerance_%=10%, Value1=Unknown, Value2=10V, ValueDisplayed=10pF
C79 C80 C98 C99: library part CMP-0120686-1, "1000 pF ±10% 10V Ceramic Capacitor X7R 0603 (1608 Metric)", Digikey Part Number=478-KGM15AR71A102KTCT-ND, Manufacturer="KYOCERA AVX", Mouser Part Number=581-0603ZC102K, Operating Temperature Range="-55°C to +125°C", TempCo=15%, Temperature Characteristic=X7R, Tolerance_%=10%, ValueDisplayed=1nF
C86 C105 C124 C127 C131: library part CMP-0096605-1, "100 pF ±5% 100V Ceramic Capacitor X7R 0603 (1608 Metric)", Digikey Part Number=478-12671-1-ND, Manufacturer="KYOCERA AVX", Mouser Part Number=581-06031C101JAT2A, Operating Temperature Range="-55°C to +125°C", TempCo=15%, Temperature Characteristic=X7R, Tolerance_%=5%, ValueDisplayed=100pF
C88 C107 C119: library part CMP-0121624-1, "10 µF ±10% 16V Ceramic Capacitor X7R 0805 (2012 Metric)", Digikey Part Number=2997-MA0805XR106K160TR-ND, Manufacturer=Meritek, Operating Temperature Range="-55°C to +125°C", TempCo=15%, Temperature Characteristic=X7R, Tolerance_%=10%, ValueDisplayed=10uF
C89 C108 C118: library part CMP-0095621-1, "22μF ±20% 10V Ceramic Capacitor X7T 0805 (2012 Metric)", Manufacturer=Murata, Mouser Part Number=81-GRT21BD71A226ME3L, Operating Temperature Range="-55°C to +125°C", TempCo=+22/-33%, Temperature Characteristic=X7T, Tolerance_%=20%, ValueDisplayed=22uF
C90 C91 C109 C110 C120 C121: library part CMP-0086419-2, "Cap Ceramic 0.015uF 50V X7R 10% Pad SMD 0603 125°C T/R", Manufacturer=Kemet, TempCo=15%, Tolerance_%=10%
C115: library part CMP-0006915-5, "CAP, CERM, 0.27 uF, 10 V, +/- 10%, X7R, 0603", Cap_Case=0603, Manufacturer=Kemet, Supplier Part Number 1=399-4914-1-ND, TempCo=X7R, Tolerance_%=10%, Value1=Unknown, Value2=10V, ValueDisplayed=0.27uF
C122: library part CMP-0081462-1, "CAP, AL, 100 µF, 25 V, +/- 20%, SMD", Cap_Case=6.3x7.7mm, Manufacturer=Nichicon, Supplier Part Number 1=493-2190-1-ND, Tolerance_%=20%, Value2=25V, ValueDisplayed=100µF
C134 C136 C139: library part CMP-0006970-4, "CAP, CERM, 82 pF, 50 V, +/- 10%, C0G/NP0, 0603", Cap_Case=0603, Manufacturer=Kemet, Supplier Part Number 1=399-1059-1-ND, TempCo=C0G/NP0, Tolerance_%=10%, Value1=Unknown, Value2=50V, ValueDisplayed=82pF
C158: library part CMP-0121052-1, "Cap Ceramic 1uF 25V X7R ±10% Pad SMD 0603 +125°C T/R", Digikey Part Number=1276-CL10B105KA8VPJCCT-ND, Manufacturer=Samsung, Mouser Part Number=187-CL10B105KA8VPJC, Operating Temperature Range="-55°C to +125°C", TempCo=15%, Temperature Characteristic=X7R, Tolerance_%=10%, ValueDisplayed=1uF
C159: library part CMP-0006753-4, "CAP, CERM, 0.1 uF, 25 V, +/- 10%, X7R, 0603", Cap_Case=0603, Manufacturer=AVX, Supplier Part Number 1=478-3714-1-ND, TempCo=X7R, Tolerance_%=10%, Value1="0.05 ohm", Value2=25V, ValueDisplayed=0.1uF
C160 C162: library part CMP-0860987-1, "CAP, CERM, 3900 pF, 100 V,+/- 5%, C0G/NP0, 0603", Cap_Case=0603, Manufacturer=TDK, TempCo=C0G/NP0, Tolerance_%=5%, Value2=100V, ValueDisplayed=3900pF
C172: library part CMP-0006853-4, "CAP, CERM, 0.01 uF, 16 V, +/- 10%, X7R, 0603", Cap_Case=0603, Manufacturer=Kemet, Supplier Part Number 1=399-7841-1-ND, TempCo=X7R, Tolerance_%=10%, Value1=Unknown, Value2=16V, ValueDisplayed=0.01uF
C173 C174 C175 C176 C177 C178 C179 C180: library part CMP-0128874-1, "2.5 µF Film Capacitor 630V 1200V (1.2kV) Polypropylene (PP), Metallized Radial - 4 Leads", Digikey Part Number=399-6457-ND, Manufacturer=KEMET, Mouser Part Number=80-C4ASPBW4250A3MJ, Operating Temperature Range="-40°C to +85°C", Tolerance_%=5%, ValueDisplayed=2.5uF
D1 D2 D3 D4 D5 D6 D7 D8 D9 D10 D11 D12 D13 D14 D15 D16 D17 D18 D19 D20 D21 D22 D23 D24: library part CMP-0077081-2, "Diode, Ultrafast, 1200 V, 1 A, SMA", Manufacturer=STMicroelectronics, Value1=1A, Value2=1.9V
D25: library part CMP-0092845-1, "LED Uni-Color Red 643nm 2-Pin Chip 0603(1608Metric) T/R", Color=Red, Digikey Part Number=475-3124-1-ND, Forward Current=2mA, Manufacturer="OSRAM Opto Semiconductors", Mouser Part Number=720-LSL29K-G1H2-1-Z, Operating Temperature Range="-40°C to +100°C"
D26 D27 D28 D29 D31 D32: library part CMP-0002894-2, "LED, Green, SMD", Color=green, Manufacturer="Wurth Elektronik", Value1=W, Value2=2V
D30: library part CMP-0028350-2, "Diode, Schottky, 30 V, 3 A, SMA", Manufacturer="Diodes Inc.", Value1=3A, Value2=0.5V
D33: library part CMP-0028951-2, "Diode, Schottky, 60 V, 0.5 A, SOD-123", Manufacturer="Diodes Inc.", Value1=0.5A, Value2=0.5V
FID1 FID2 FID3: library part CMP-0077181-1, "Fiducial mark.  There is nothing to buy or mount.", Manufacturer=N/A
H1 H2 H3 H4 H5 H6 H7 H8 H9 H10 H12 H13 H14 H15 H16: library part CMP-0003617-1, "Machine Screw, Round, #4-40 x 1/4, Nylon, Philips panhead", Manufacturer="B&F Fastener Supply", Supplier Part Number 1=H542-ND
J1 J2 J3 J4 J7 J8 J9 J10 J24 J25 J26 J27: library part CMP-0082272-1, "Receptacle, 2.54mm, 3x2, Gold, SMT", Color=Black, Current_A=4.1A, Manufacturer=Samtec, Supplier Part Number 1=SAM9484-ND, Voltage_V=400V
J5 J6 J11 J12: library part CMP-0054757-1, "Power Element Bush, M4, 12, TH", Manufacturer="Wurth Elektronik", Supplier Part Number 1=732-3207-ND
J13 J14 J15 J16: library part CMP-0127514-1, "Conn Socket Strip SKT 10 POS 2.54mm Solder ST Top Entry SMD Tube", Current_A=4.1A, Digikey Part Number=SAM12618-ND, Manufacturer=Samtec, Mouser Part Number=200-HLE10502GDVBEA, Operating Temperature Range="-55°C to +125°C", Voltage_V=566V
J17: library part CMP-0003814-2, "C2000 controlCARD-120HSEC connector, SMT", Manufacturer=Samtec
J18: library part CMP-0003859-2, "C2000 controlCARD-180HSEC (60-pin addon) connector, SMT", Manufacturer=Samtec
J19: library part CMP-0054804-1, "Header, 2.54mm, 10x1, Gold, TH", Color=Black, Manufacturer="Wurth Elektronik", Supplier Part Number 1=732-2670-ND
J20 J22 J23: library part CMP-0075491-1, "Header, 100mil, 2x1, Tin, SMD", Color=Black, Current_A=5.4A, Manufacturer=Samtec, Supplier Part Number 1=77P4673, Voltage_V=475V
J21: library part CMP-0075012-1, "Power Jack, SMT", Manufacturer="CUI Inc.", Supplier Part Number 1=CP-002AHPJDKR-ND
J28 J29: library part CMP-0122568-1, "Mini-Latch™ Wire-to-Board Header, Vertical, with Friction Ramp, 3 Circuits, Gold (Au) Plating", Current_A=3A, Digikey Part Number=23-0022111031-ND, Manufacturer=Molex, Mouser Part Number=538-22-11-1031, Operating Temperature Range="-40°C to +105°C", Voltage_V=250V
L1 L2 L3: library part CMP-0062508-2, "Inductor, Shielded, Ferrite, 47 uH, 0.06 A, 1.7 ohm, SMD", Manufacturer=TDK, Supplier Part Number 1=445-1910-1-ND, Value1="1.7 ohm", Value2=0.06A, ValueDisplayed=47uH
L7: library part CMP-0128921-1, "4.7 µH Shielded Molded Inductor 5.3 A 36.96mOhm Max Nonstandard", Digikey Part Number=732-74439324047CT-ND, Manufacturer=Wurth, Mouser Part Number=710-74439324047, Operating Temperature Range="-40°C to +125°C", Self Resonant Frequency=28MHz, Test Frequency=100kHz, Tolerance_%=20%
LBL1: library part CMP-0003625-1, "Thermal Transfer Printable Labels, 0.650\" W x 0.200\" H - 10,000 per roll", Manufacturer=Brady, Supplier Part Number 1=97C5133
Logo1: library part CMP-0074844-1
Logo3: library part CMP-0074847-1, "FCC_disclaimer"
Logo4: library part CMP-0074769-1
LOGO6: library part CMP-0074837-2, "IEC 61010-1 Hot Surface Warning", Manufacturer="Texas Instruments"
LOGO7: library part CMP-0074835-1, "IEC 61010-1 High Voltage Warning"
MD1 MD2: library part CMP-0128745-2, "3300V 22.5mΩ Full-Bridge / Dual-Half-Bridge SiC Module", Drain To Source Breakdown Voltage=3300V, Input Capacitance At Vds="13820pF @ 2000V", Manufacturer="Navitas Semiconductor", Operating Temperature Range="-55°C to +175°C", Typ Forward Diode Voltage=4V
Q1: library part CMP-0000585-1, "MOSFET, N-CH, 30 V, 22 A, DQK0006C (WSON-6)", Alternate Manufacturer=None, Manufacturer="Texas Instruments", Supplier Part Number 1=296-37193-1-ND, Value1=0.02, Value2="2.4 nC"
Q2: library part CMP-0089138-1, "MOSFET N-CH 30V 5.8A SOT23", Digikey Part Number=DMN3042L-13DI-ND, Drain To Source Breakdown Voltage=30V, Input Capacitace At Vds="570pF @ 15V", Manufacturer=Diodes, Mouser Part Number=621-DMN3042L-13, Operating Temperature Range="-55°C to +150°C", Power_W=0.72W, Pulse Drain Current=30A, Typ Forward Diode Voltage=0.7V
R1 R2 R3 R4 R5 R6 R7 R8 R9 R10 R11 R12 R13 R14 R15 R16 R21 R22 R23 R24 R25 R28 R31 R32 R33 R34 R35 R36 R37 R38 R39 R40: library part CMP-0017868-2, "RES, 120 k, 1%, 0.25 W, 1206", Manufacturer="Yageo America", Power_W=250mW, Supplier Part Number 1=311-120KFRCT-ND, TempCo="100 ppm/C", Tolerance_%=1%, Value2=0.25W, Value_Code=120k
R17 R18 R19 R20 R26 R27 R29 R30 R45 R46 R47 R53 R54 R55 R89 R91 R92 R93 R120 R121 R122 R123 R149 R150 R204 R205: library part CMP-0022684-3, "RES, 10.0 k, 1%, 0.1 W, 0603", Manufacturer=Panasonic, Power_W=100mW, Supplier Part Number 1=P10.0KHCT-ND, TempCo="100 ppm/C", Tolerance_%=1%, Value2=0.1W, Value_Code=10k0, ValueDisplayed=10.0k
R41 R42 R43: library part CMP-0065757-2, "RES, 0.0005, 1%, 3 W, 4026", Manufacturer=Vishay-Dale, Power_W=3W, Supplier Part Number 1=WSLR-.0005CT-ND, TempCo="75 ppm/C", Tolerance_%=1%, Value_Code=L5000, ValueDisplayed=0.0005
R44 R51 R56 R57 R67 R68 R75 R76 R77 R78 R80 R84 R85 R86 R94 R97 R109 R110 R111 R112 R113 R114 R115 R117 R118 R124 R186 R189 R191: library part CMP-0025880-3, "RES, 47, 5%, 0.1 W, AEC-Q200 Grade 0, 0603", Manufacturer=Panasonic, Power_W=100mW, Supplier Part Number 1=P47GCT-ND, TempCo="200 ppm/C", Tolerance_%=5%, Value2=0.1W, Value_Code=47R0, ValueDisplayed=47
R48 R49 R50 R52 R147 R148: library part CMP-0082532-1, "RES, 499, 1%, 0.1 W, 0603", Manufacturer=Vishay-Dale, Power_W=100mW, Supplier Part Number 1=541-3986-1-ND, TempCo="100 ppm/C", Tolerance_%=1%, Value2=0.1W, Value_Code=499R, ValueDisplayed=499
R58 R59 R60 R61 R62 R63 R64 R65 R66 R69 R70 R71 R72 R73 R74 R79 R81 R82 R83 R87 R88 R90 R95 R96 R98 R99 R100 R101 R102 R103 R104 R105 R106 R107 R108 R116 R119 R125 R126 R127 R128 R129 R130 R131 R132 R133 R215 R216 R217 R218 R219: library part CMP-0097467-1, "0 Ohms Jumper 0.125W, 1/8W Chip Resistor 0603 (1608 Metric) Automotive AEC-Q200 Thick Film", Digikey Part Number=10-ERJ-H3G0R00VCT-ND, Manufacturer=Panasonic, Mouser Part Number=667-ERJ-H3G0R00V, Operating Temperature Range="-55°C to +175°C", Power_W=125mW
R134: library part CMP-0023128-4, "RES, 470 k, 1%, 0.1 W, 0603", Manufacturer=Yageo, Power_W=100mW, Supplier Part Number 1=311-470KHRCT-ND, TempCo="100 ppm/C", Tolerance_%=1%, Value2=0.1W, Value_Code=470k
R135 R139 R141 R143: library part CMP-0023133-5, "RES, 47.0 k, 1%, 0.1 W, 0603", Manufacturer=Yageo, Power_W=100mW, Supplier Part Number 1=311-47.0KHRCT-ND, TempCo="100 ppm/C", Tolerance_%=1%, Value2=0.1W, Value_Code=47k0, ValueDisplayed=47.0k
R136: library part CMP-0022870-5, "RES, 1.10 k, 1%, 0.1 W, 0603", Manufacturer=Yageo, Power_W=100mW, Supplier Part Number 1=311-1.10KHRCT-ND, TempCo="100 ppm/C", Tolerance_%=1%, Value2=0.1W, Value_Code=1k10, ValueDisplayed=1.10k
R137: library part CMP-0023203-5, "RES, 5.60 k, 1%, 0.1 W, 0603", Manufacturer=Yageo, Power_W=100mW, Supplier Part Number 1=311-5.60KHRCT-ND, TempCo="100 ppm/C", Tolerance_%=1%, Value2=0.1W, Value_Code=5k60, ValueDisplayed=5.60k
R138: library part CMP-0022763-5, "RES, 11.0 k, 1%, 0.1 W, 0603", Manufacturer=Yageo, Power_W=100mW, Supplier Part Number 1=311-11.0KHRCT-ND, TempCo="100 ppm/C", Tolerance_%=1%, Value2=0.1W, Value_Code=11k0, ValueDisplayed=11.0k
R140: library part CMP-0023000-5, "RES, 2.00 k, 1%, 0.1 W, 0603", Manufacturer=Yageo, Power_W=100mW, Supplier Part Number 1=311-2.00KHRCT-ND, TempCo="100 ppm/C", Tolerance_%=1%, Value2=0.1W, Value_Code=2k00, ValueDisplayed=2.00k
